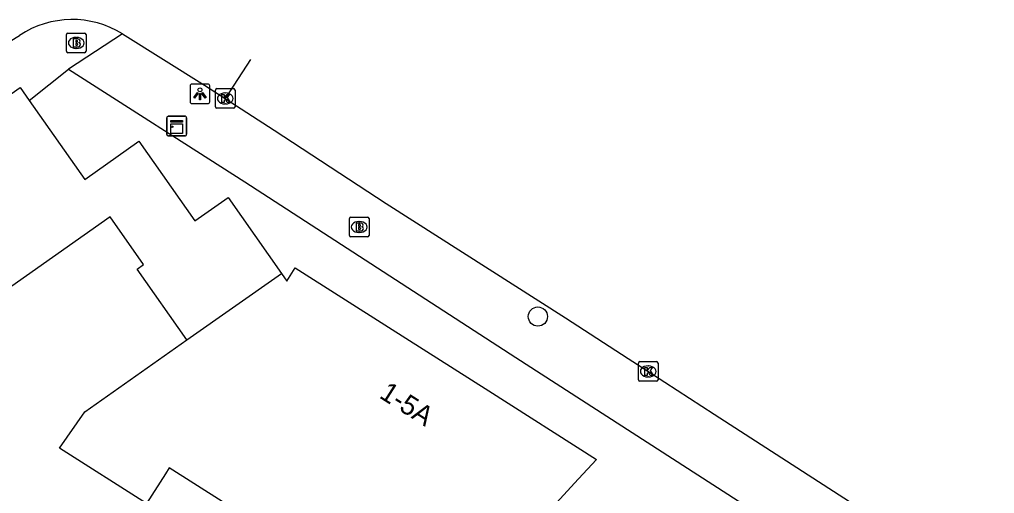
# Model space of a CAD drawing. Extents: x 159822 to 160765, y 380693 to 381634.
# Drawn here: x 160302.75 to 160352.34, y 381609.6 to 381633.7 of the extents above; entities that cross this region are included whole.
import ezdxf

# ---------------------------------------------------------------- set-up
doc = ezdxf.new("R2010")
doc.units = 0
for name, color, linetype in [('IMGEO_Boom', 7, 'Continuous'), ('IMGEO_Brandkraan', 7, 'Continuous'), ('IMGEO_Kast', 7, 'Continuous'), ('IMGEO_Kolk', 7, 'Continuous'), ('IMGEO_Lichtpunt', 7, 'Continuous'), ('IMGEO_Pand', 7, 'Continuous'), ('IMGEO_Pand_nummerreeks', 7, 'Continuous'), ('IMGEO_Rijbaan_lokaal_open', 7, 'Continuous'), ('IMGEO_Voetpad_open', 7, 'Continuous')]:
    doc.layers.add(name, color=color, linetype=linetype)

msp = doc.modelspace()

# ---------------------------------------------------------------- linework, layer by layer
at = {"layer": 'IMGEO_Boom'}
msp.add_circle((160329.118, 381618.597), 0.489, dxfattribs=at)
at = {"layer": 'IMGEO_Brandkraan'}
for p, q in [((160305.134, 381632.087), (160305.134, 381632.939)), ((160305.209, 381633.013), (160306.061, 381633.013)), ((160305.622, 381632.793), (160305.647, 381632.793)), ((160306.135, 381632.939), (160306.135, 381632.087)), ((160305.645, 381632.233), (160305.62, 381632.233)), ((160306.061, 381632.013), (160305.209, 381632.013)), ((160319.529, 381622.726), (160319.529, 381623.578)), ((160319.604, 381623.652), (160320.456, 381623.652)), ((160320.017, 381623.432), (160320.042, 381623.432)), ((160320.53, 381623.578), (160320.53, 381622.726)), ((160320.04, 381622.872), (160320.015, 381622.872)), ((160320.456, 381622.652), (160319.604, 381622.652))]:
    msp.add_line(p, q, dxfattribs=at)
for points in [[(160305.134, 381632.087), (160305.134, 381632.939)], [(160305.209, 381633.013), (160306.061, 381633.013)], [(160305.482, 381632.713), (160305.482, 381632.313), (160305.695, 381632.313)], [(160305.713, 381632.713), (160305.482, 381632.713)], [(160306.135, 381632.939), (160306.135, 381632.087)], [(160305.661, 381632.632), (160305.607, 381632.632), (160305.607, 381632.556)], [(160305.607, 381632.556), (160305.66, 381632.556)], [(160305.669, 381632.48), (160305.607, 381632.48), (160305.607, 381632.399)], [(160305.607, 381632.399), (160305.669, 381632.399)], [(160306.061, 381632.013), (160305.209, 381632.013)], [(160319.529, 381622.726), (160319.529, 381623.578)], [(160319.604, 381623.652), (160320.456, 381623.652)], [(160319.877, 381623.352), (160319.877, 381622.952), (160320.09, 381622.952)], [(160320.108, 381623.352), (160319.877, 381623.352)], [(160320.056, 381623.271), (160320.002, 381623.271), (160320.002, 381623.195)], [(160320.53, 381623.578), (160320.53, 381622.726)], [(160320.002, 381623.195), (160320.055, 381623.195)], [(160320.064, 381623.119), (160320.002, 381623.119), (160320.002, 381623.038)], [(160320.002, 381623.038), (160320.064, 381623.038)], [(160320.456, 381622.652), (160319.604, 381622.652)]]:
    msp.add_lwpolyline(points, dxfattribs=at)
for centre, radius, start, end in [((160305.211, 381632.937), 0.0765, 91.552, 178.448), ((160305.211, 381632.937), 0.0765, 91.552, 178.448), ((160305.717, 381632.568), 0.145, 59.4692, 91.5367), ((160305.742, 381632.615), 0.0922, 285.5137, 58.1501), ((160306.059, 381632.937), 0.0765, 1.552, 88.448), ((160306.059, 381632.937), 0.0765, 1.552, 88.448), ((160305.662, 381632.594), 0.0379, 267.8285, 90.9355), ((160305.67, 381632.439), 0.0404, 269.8759, 90.5077), ((160305.701, 381632.564), 0.251, 268.6676, 293.5347), ((160305.747, 381632.423), 0.105, 301.3115, 78.989), ((160305.211, 381632.089), 0.0765, 181.552, 268.448), ((160305.211, 381632.089), 0.0765, 181.552, 268.448), ((160306.059, 381632.089), 0.0765, 271.552, 358.448), ((160306.059, 381632.089), 0.0765, 271.552, 358.448), ((160319.606, 381623.576), 0.0765, 91.552, 178.448), ((160319.606, 381623.576), 0.0765, 91.552, 178.448), ((160320.057, 381623.233), 0.0379, 267.8285, 90.9355), ((160320.112, 381623.207), 0.145, 59.4692, 91.5367), ((160320.137, 381623.254), 0.0922, 285.5137, 58.1501), ((160320.454, 381623.576), 0.0765, 1.552, 88.448), ((160320.454, 381623.576), 0.0765, 1.552, 88.448), ((160320.065, 381623.078), 0.0404, 269.8759, 90.5077), ((160320.096, 381623.203), 0.251, 268.6676, 293.5347), ((160320.142, 381623.062), 0.105, 301.3115, 78.989), ((160319.606, 381622.728), 0.0765, 181.552, 268.448), ((160319.606, 381622.728), 0.0765, 181.552, 268.448), ((160320.454, 381622.728), 0.0765, 271.552, 358.448), ((160320.454, 381622.728), 0.0765, 271.552, 358.448)]:
    msp.add_arc(centre, radius, start, end, dxfattribs=at)
for centre, major_axis, ratio, start_param, end_param in [((160305.621, 381632.513), (-0.387, 0.002), 0.722429, 4.712389, 7.853982), ((160305.646, 381632.513), (-0.39, 0.002), 0.717154, 1.570796, 4.712389), ((160320.016, 381623.152), (-0.387, 0.002), 0.722429, 4.712389, 7.853982), ((160320.041, 381623.152), (-0.39, 0.002), 0.717154, 1.570796, 4.712389)]:
    msp.add_ellipse(centre, major_axis=major_axis, ratio=ratio, start_param=start_param, end_param=end_param, dxfattribs=at)
at = {"layer": 'IMGEO_Kast'}
for p, q in [((160310.245, 381627.86), (160310.245, 381628.701)), ((160310.245, 381628.701), (160310.245, 381627.86)), ((160310.32, 381628.785), (160311.161, 381628.785)), ((160311.161, 381628.785), (160310.32, 381628.785)), ((160311.245, 381628.71), (160311.245, 381627.869)), ((160311.245, 381627.869), (160311.245, 381628.71)), ((160311.17, 381627.785), (160310.329, 381627.785)), ((160310.329, 381627.785), (160311.17, 381627.785))]:
    msp.add_line(p, q, dxfattribs=at)
for points in [[(160310.44, 381628.575), (160311.04, 381628.575), (160311.04, 381628.49), (160310.44, 381628.49), (160310.44, 381628.575)], [(160310.44, 381628.4), (160311.04, 381628.4), (160311.04, 381627.911), (160310.44, 381627.911), (160310.44, 381628.4)]]:
    msp.add_lwpolyline(points, dxfattribs=at)
msp.add_circle((160310.524, 381628.249), 0.0377, dxfattribs=at)
for centre, start, end in [((160310.323, 381628.707), 92.4484, 184.2845), ((160310.323, 381628.707), 92.4484, 184.2845), ((160311.167, 381628.707), 2.4484, 94.2845), ((160311.167, 381628.707), 2.4484, 94.2845), ((160310.323, 381627.863), 182.4484, 274.2845), ((160310.323, 381627.863), 182.4484, 274.2845), ((160311.167, 381627.863), 272.4484, 4.2845), ((160311.167, 381627.863), 272.4484, 4.2845)]:
    msp.add_arc(centre, 0.0779, start, end, dxfattribs=at)
at = {"layer": 'IMGEO_Kolk'}
for p, q in [((160312.789, 381630.188), (160313.641, 381630.188)), ((160312.714, 381629.262), (160312.714, 381630.114)), ((160313.202, 381629.968), (160313.227, 381629.968)), ((160313.715, 381630.114), (160313.715, 381629.262)), ((160313.641, 381629.188), (160312.789, 381629.188)), ((160313.225, 381629.408), (160313.2, 381629.408)), ((160334.306, 381616.308), (160335.158, 381616.308)), ((160334.231, 381615.382), (160334.231, 381616.234)), ((160334.719, 381616.088), (160334.744, 381616.088)), ((160335.232, 381616.234), (160335.232, 381615.382)), ((160335.158, 381615.308), (160334.306, 381615.308)), ((160334.742, 381615.528), (160334.717, 381615.528))]:
    msp.add_line(p, q, dxfattribs=at)
for points in [[(160312.789, 381630.188), (160313.641, 381630.188)], [(160312.714, 381629.262), (160312.714, 381630.114)], [(160313.035, 381629.888), (160313.158, 381629.888), (160313.158, 381629.737), (160313.288, 381629.888), (160313.452, 381629.888), (160313.306, 381629.737), (160313.459, 381629.488), (160313.307, 381629.488), (160313.222, 381629.652), (160313.158, 381629.585), (160313.158, 381629.488), (160313.035, 381629.488), (160313.035, 381629.888)], [(160313.715, 381630.114), (160313.715, 381629.262)], [(160313.641, 381629.188), (160312.789, 381629.188)], [(160334.306, 381616.308), (160335.158, 381616.308)], [(160334.231, 381615.382), (160334.231, 381616.234)], [(160334.552, 381616.008), (160334.675, 381616.008), (160334.675, 381615.857), (160334.805, 381616.008), (160334.969, 381616.008), (160334.823, 381615.857), (160334.976, 381615.608), (160334.824, 381615.608), (160334.739, 381615.772), (160334.675, 381615.705), (160334.675, 381615.608), (160334.552, 381615.608), (160334.552, 381616.008)], [(160335.232, 381616.234), (160335.232, 381615.382)], [(160335.158, 381615.308), (160334.306, 381615.308)]]:
    msp.add_lwpolyline(points, dxfattribs=at)
for centre, start, end in [((160312.791, 381630.112), 91.552, 178.448), ((160312.791, 381630.112), 91.552, 178.448), ((160313.639, 381630.112), 1.552, 88.448), ((160313.639, 381630.112), 1.552, 88.448), ((160312.791, 381629.264), 181.552, 268.448), ((160312.791, 381629.264), 181.552, 268.448), ((160313.639, 381629.264), 271.552, 358.448), ((160313.639, 381629.264), 271.552, 358.448), ((160334.308, 381616.232), 91.552, 178.448), ((160334.308, 381616.232), 91.552, 178.448), ((160335.156, 381616.232), 1.552, 88.448), ((160335.156, 381616.232), 1.552, 88.448), ((160334.308, 381615.384), 181.552, 268.448), ((160334.308, 381615.384), 181.552, 268.448), ((160335.156, 381615.384), 271.552, 358.448), ((160335.156, 381615.384), 271.552, 358.448)]:
    msp.add_arc(centre, 0.0765, start, end, dxfattribs=at)
for centre, major_axis, ratio, start_param, end_param in [((160313.201, 381629.688), (-0.387, 0.002), 0.722429, 4.712389, 7.853982), ((160313.226, 381629.688), (-0.39, 0.002), 0.717154, 1.570796, 4.712389), ((160334.718, 381615.808), (-0.387, 0.002), 0.722429, 4.712389, 7.853982), ((160334.743, 381615.808), (-0.39, 0.002), 0.717154, 1.570796, 4.712389)]:
    msp.add_ellipse(centre, major_axis=major_axis, ratio=ratio, start_param=start_param, end_param=end_param, dxfattribs=at)
at = {"layer": 'IMGEO_Lichtpunt'}
for p, q in [((160311.43, 381630.328), (160311.43, 381629.521)), ((160311.43, 381630.328), (160311.43, 381629.521)), ((160312.332, 381630.423), (160311.524, 381630.423)), ((160312.332, 381630.423), (160311.524, 381630.423)), ((160312.426, 381629.521), (160312.426, 381630.328)), ((160312.426, 381629.521), (160312.426, 381630.328)), ((160311.524, 381629.427), (160312.332, 381629.427)), ((160311.524, 381629.427), (160312.332, 381629.427))]:
    msp.add_line(p, q, dxfattribs=at)
for points in [[(160311.804, 381629.992), (160311.843, 381629.964), (160311.655, 381629.702), (160311.617, 381629.729), (160311.804, 381629.992)], [(160311.906, 381629.944), (160311.953, 381629.944), (160311.953, 381629.622), (160311.906, 381629.622), (160311.906, 381629.944)], [(160312.016, 381629.964), (160312.054, 381629.991), (160312.241, 381629.729), (160312.202, 381629.701), (160312.016, 381629.964)]]:
    msp.add_lwpolyline(points, dxfattribs=at)
msp.add_circle((160311.929, 381630.126), 0.0994, dxfattribs=at)
for centre, start, end in [((160311.524, 381630.328), 90, 180), ((160311.524, 381630.328), 90, 180), ((160312.332, 381630.328), 0, 90), ((160312.332, 381630.328), 0, 90), ((160311.524, 381629.521), 180, 270), ((160311.524, 381629.521), 180, 270), ((160312.332, 381629.521), 270, 0), ((160312.332, 381629.521), 270, 360)]:
    msp.add_arc(centre, 0.0946, start, end, dxfattribs=at)
at = {"layer": 'IMGEO_Pand'}
for points in [[(160295.534, 381625.148), (160302.776, 381630.25), (160303.241, 381629.59)], [(160303.241, 381629.59), (160306.074, 381625.569), (160308.827, 381627.509), (160311.677, 381623.464), (160313.362, 381624.651), (160316.079, 381620.795)], [(160311.268, 381617.409), (160308.727, 381621.013), (160309.062, 381621.249), (160307.356, 381623.668), (160300.154, 381618.593), (160295.534, 381625.148)], [(160311.268, 381617.409), (160316.079, 381620.795)], [(160316.079, 381620.795), (160316.355, 381620.403), (160316.779, 381621.071), (160321.523, 381618.056), (160326.62, 381614.817), (160332.106, 381611.331), (160331.19, 381610.342), (160328.722, 381607.676)], [(160323.65, 381602.47), (160310.369, 381610.909), (160310.177, 381610.607), (160309.216, 381609.096), (160304.785, 381611.911), (160306.078, 381613.752), (160311.268, 381617.409)]]:
    msp.add_lwpolyline(points, dxfattribs=at)
at = {"layer": 'IMGEO_Rijbaan_lokaal_open'}
for points in [[(160298.977, 381630.6), (160302.75, 381632.897)], [(160307.987, 381632.978), (160312.158, 381630.368), (160313.203, 381629.689)], [(160314.492, 381631.674), (160313.203, 381629.689)], [(160313.203, 381629.689), (160315.698, 381628.07), (160321.397, 381624.349), (160330.518, 381618.527), (160333.71, 381616.468), (160334.954, 381615.665), (160338.093, 381613.627), (160402.863, 381571.862), (160406.731, 381569.352), (160407.094, 381569.117), (160410.289, 381567.091), (160413.073, 381565.294), (160415.354, 381563.821)]]:
    msp.add_lwpolyline(points, dxfattribs=at)
msp.add_arc((160305.432, 381628.835), 4.867, 58.3348, 123.4374, dxfattribs=at)
at = {"layer": 'IMGEO_Voetpad_open'}
for points in [[(160307.987, 381632.978), (160305.249, 381631.183)], [(160303.241, 381629.59), (160305.249, 381631.183)], [(160305.249, 381631.183), (160314.21, 381625.449), (160327.997, 381616.523), (160405.634, 381566.488), (160408.36, 381564.734)]]:
    msp.add_lwpolyline(points, dxfattribs=at)

# ---------------------------------------------------------------- texts
at = {"layer": 'IMGEO_Pand_nummerreeks'}
msp.add_text('1-5A', height=1, rotation=327.5649, dxfattribs=at).set_placement((160321.002, 381614.501))

doc.saveas('drawing.dxf')
